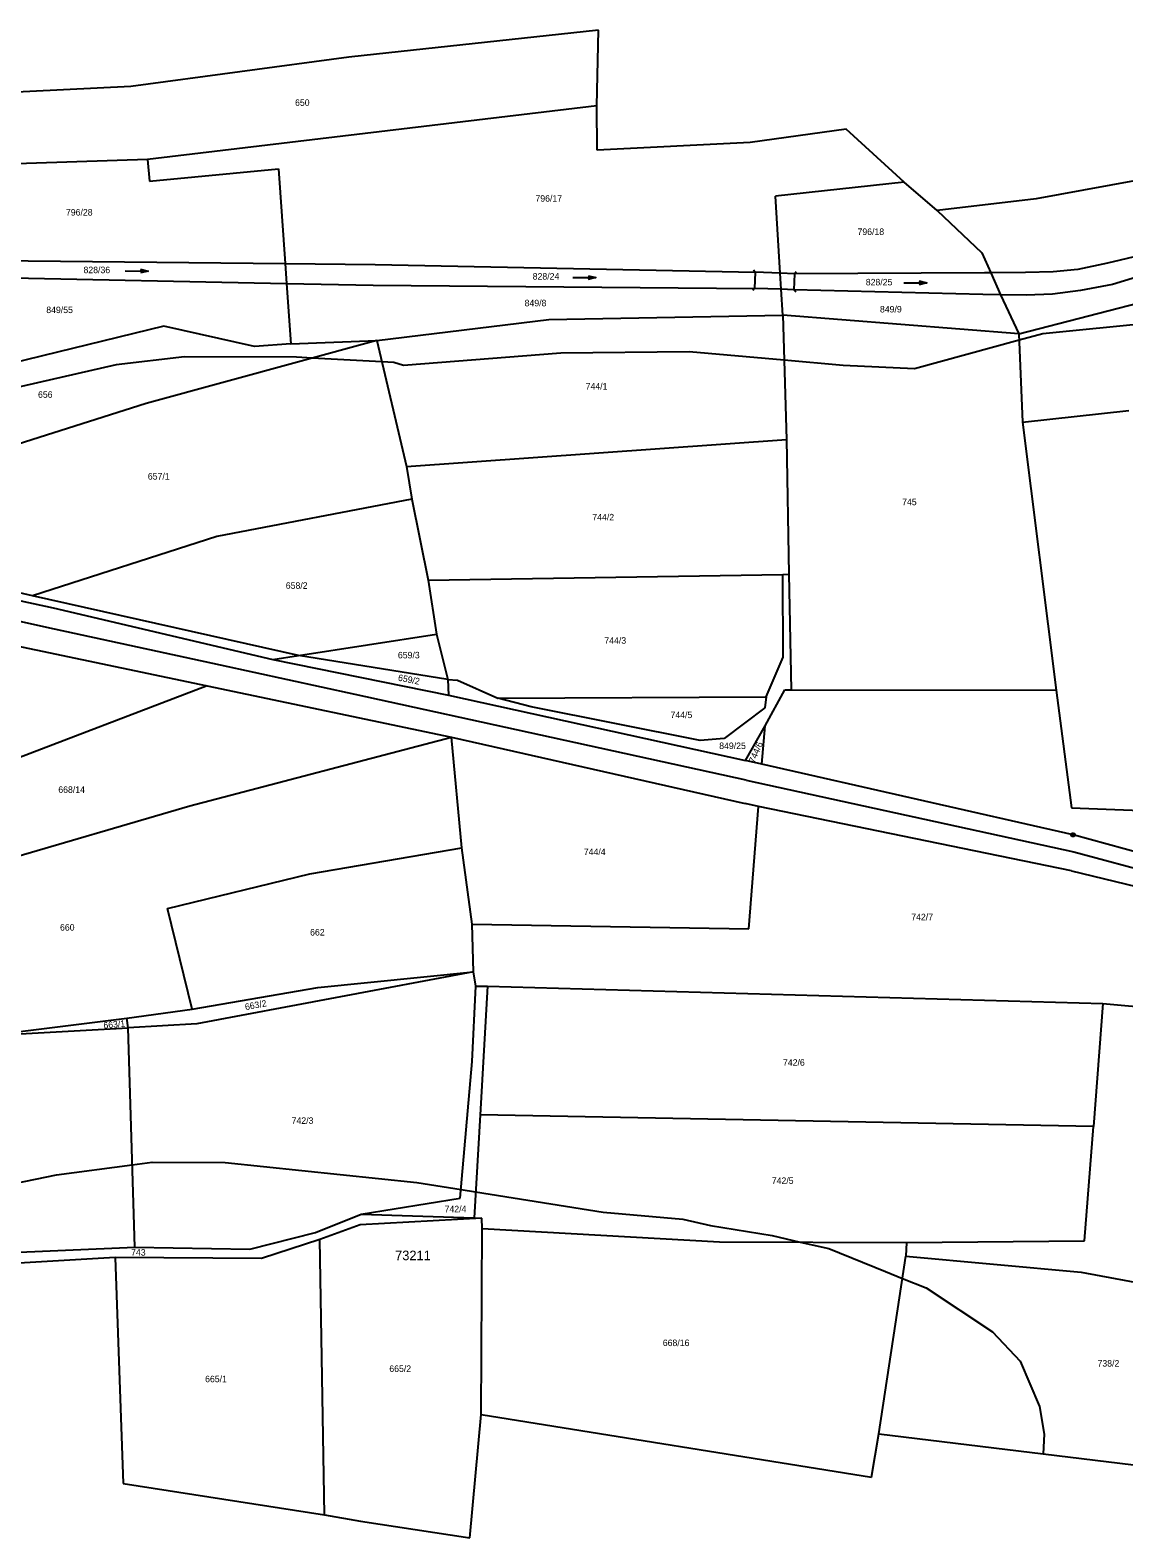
# Model space of a CAD drawing. Extents: x -789470 to -786707, y -1118640 to -1114455.
# Drawn here: x -789008.6 to -788723, y -1114869.5 to -1114476 of the extents above; entities that cross this region are included whole.
import ezdxf

# ---------------------------------------------------------------- set-up
doc = ezdxf.new("R2010")
doc.units = 0
for name, color, linetype in [('1', 7, 'Continuous'), ('11', 7, 'Continuous'), ('2', 7, 'Continuous'), ('3', 7, 'Continuous'), ('4', 7, 'Continuous'), ('6', 7, 'Continuous'), ('8', 7, 'Continuous')]:
    doc.layers.add(name, color=color, linetype=linetype)

msp = doc.modelspace()

# ---------------------------------------------------------------- linework, layer by layer
at = {"layer": '1'}
for p, q in [((-788860.22, -1114476), (-788925.35, -1114483.02)), ((-788860.65, -1114495.76), (-788860.22, -1114476)), ((-788925.35, -1114483.02), (-788982.26, -1114490.73)), ((-788982.26, -1114490.73), (-789030.25, -1114493.04)), ((-788860.65, -1114495.76), (-788977.92, -1114509.77)), ((-788860.57, -1114507.36), (-788860.65, -1114495.76)), ((-788795.54, -1114501.83), (-788820.58, -1114505.34)), ((-788780.41, -1114515.68), (-788795.54, -1114501.83)), ((-788820.58, -1114505.34), (-788860.57, -1114507.36)), ((-788977.92, -1114509.77), (-789040.51, -1114511.82)), ((-788977.92, -1114509.77), (-788977.42, -1114515.41)), ((-788977.42, -1114515.41), (-788943.76, -1114512.16)), ((-788943.76, -1114512.16), (-788942, -1114536.9)), ((-788705.61, -1114512.65), (-788745.95, -1114520.06)), ((-788780.41, -1114515.68), (-788813.99, -1114519.29)), ((-788812.75, -1114539.42), (-788813.99, -1114519.29)), ((-788771.75, -1114523.06), (-788780.41, -1114515.68)), ((-788745.95, -1114520.06), (-788771.75, -1114523.06)), ((-788771.75, -1114523.06), (-788760.13, -1114534.14)), ((-788750.44, -1114555.28), (-788649.58, -1114529.02)), ((-788760.13, -1114534.14), (-788757.8, -1114539.34)), ((-788718.84, -1114534.86), (-788727.34, -1114536.81)), ((-789021.34, -1114536.08), (-788942, -1114536.9)), ((-788942, -1114536.9), (-788941.63, -1114542.1)), ((-788942, -1114536.9), (-788918.51, -1114537.14)), ((-788918.51, -1114537.14), (-788819.27, -1114539.17)), ((-788741.49, -1114539.08), (-788748.69, -1114539.26)), ((-788735.01, -1114538.51), (-788741.49, -1114539.08)), ((-788727.34, -1114536.81), (-788735.01, -1114538.51)), ((-789021.49, -1114540.49), (-788941.63, -1114542.1)), ((-788941.63, -1114542.1), (-788940.51, -1114557.89)), ((-788941.63, -1114542.1), (-788919.01, -1114542.55)), ((-788919.01, -1114542.55), (-788819.42, -1114543.39)), ((-788812.75, -1114539.42), (-788819.27, -1114539.17)), ((-788812.49, -1114543.63), (-788812.75, -1114539.42)), ((-788809.05, -1114539.56), (-788812.75, -1114539.42)), ((-788759.42, -1114539.35), (-788809.05, -1114539.56)), ((-788757.8, -1114539.34), (-788759.42, -1114539.35)), ((-788748.69, -1114539.26), (-788757.8, -1114539.34)), ((-788757.8, -1114539.34), (-788755.23, -1114545.05)), ((-788726.02, -1114542.39), (-788734.31, -1114543.93)), ((-788717.73, -1114539.86), (-788726.02, -1114542.39)), ((-788812.49, -1114543.63), (-788819.42, -1114543.39)), ((-788812.08, -1114550.36), (-788812.49, -1114543.63)), ((-788809.16, -1114543.75), (-788812.49, -1114543.63)), ((-788759.81, -1114544.99), (-788809.16, -1114543.75)), ((-788755.23, -1114545.05), (-788759.81, -1114544.99)), ((-788755.23, -1114545.05), (-788750.44, -1114555.28)), ((-788748.54, -1114545.13), (-788755.23, -1114545.05)), ((-788741.64, -1114544.89), (-788748.54, -1114545.13)), ((-788734.31, -1114543.93), (-788741.64, -1114544.89)), ((-788873.19, -1114551.53), (-788812.08, -1114550.36)), ((-788750.44, -1114555.28), (-788812.08, -1114550.36)), ((-788812.08, -1114550.36), (-788811.07, -1114582.85)), ((-788973.71, -1114553.25), (-789058.59, -1114574)), ((-788950.02, -1114558.61), (-788973.71, -1114553.25)), ((-788918.07, -1114556.96), (-788873.19, -1114551.53)), ((-788918.07, -1114556.96), (-788978.27, -1114573.47)), ((-788940.51, -1114557.89), (-788950.02, -1114558.61)), ((-788940.51, -1114557.89), (-788918.07, -1114556.96)), ((-788918.07, -1114556.96), (-788910.33, -1114589.9)), ((-788750.44, -1114555.28), (-788749.5, -1114578.32)), ((-788978.27, -1114573.47), (-789057.48, -1114598.57)), ((-788749.5, -1114578.32), (-788721.73, -1114575.26)), ((-788749.5, -1114578.32), (-788740.67, -1114648.25)), ((-788910.33, -1114589.9), (-788811.07, -1114582.85)), ((-788811.07, -1114582.85), (-788810.49, -1114618)), ((-788910.33, -1114589.9), (-788908.92, -1114598.39)), ((-788908.92, -1114598.39), (-788959.84, -1114608.12)), ((-788908.92, -1114598.39), (-788904.63, -1114619.6)), ((-788959.84, -1114608.12), (-789007.92, -1114623.62)), ((-789061.16, -1114614.19), (-789002.52, -1114626.82)), ((-789007.92, -1114623.62), (-789043.9, -1114615.51)), ((-788904.63, -1114619.6), (-788812.08, -1114618.04)), ((-788904.63, -1114619.6), (-788902.51, -1114633.65)), ((-788812.08, -1114618.04), (-788810.49, -1114618)), ((-788811.99, -1114639.69), (-788812.08, -1114618.04)), ((-788810.49, -1114618), (-788809.85, -1114648.14)), ((-788938.55, -1114639.25), (-789007.92, -1114623.62)), ((-789002.52, -1114626.82), (-788945.18, -1114640.28)), ((-789033.04, -1114632.27), (-788962.34, -1114647.14)), ((-788938.55, -1114639.25), (-788902.51, -1114633.65)), ((-788902.51, -1114633.65), (-788899.53, -1114645.51)), ((-788945.18, -1114640.28), (-788938.55, -1114639.25)), ((-788945.18, -1114640.28), (-788899.34, -1114649.59)), ((-788899.53, -1114645.51), (-788938.55, -1114639.25)), ((-788816.4, -1114650.04), (-788811.99, -1114639.69)), ((-788962.34, -1114647.14), (-789068.19, -1114687.52)), ((-788962.34, -1114647.14), (-788898.55, -1114660.57)), ((-788899.53, -1114645.51), (-788896.98, -1114645.63)), ((-788899.53, -1114645.51), (-788899.34, -1114649.59)), ((-788896.98, -1114645.63), (-788886.49, -1114650.35)), ((-788816.69, -1114657.55), (-788811.51, -1114648.21)), ((-788811.51, -1114648.21), (-788809.85, -1114648.14)), ((-788809.85, -1114648.14), (-788740.67, -1114648.25)), ((-788740.67, -1114648.25), (-788736.73, -1114679)), ((-788899.34, -1114649.59), (-788821.82, -1114666.61)), ((-788886.49, -1114650.35), (-788816.4, -1114650.04)), ((-788877.76, -1114652.59), (-788886.49, -1114650.35)), ((-788833.62, -1114661.44), (-788877.76, -1114652.59)), ((-788816.78, -1114652.84), (-788827.38, -1114660.85)), ((-788816.4, -1114650.04), (-788816.78, -1114652.84)), ((-788966.91, -1114678.44), (-788898.55, -1114660.57)), ((-788895.88, -1114689.44), (-788898.55, -1114660.57)), ((-788898.55, -1114660.57), (-788821.94, -1114677.87)), ((-788827.38, -1114660.85), (-788833.62, -1114661.44)), ((-788821.82, -1114666.61), (-788816.69, -1114657.55)), ((-788817.52, -1114667.59), (-788816.69, -1114657.55)), ((-788817.52, -1114667.59), (-788821.82, -1114666.61)), ((-788736.3, -1114686.03), (-788817.52, -1114667.59)), ((-789033.32, -1114697.94), (-788966.91, -1114678.44)), ((-788818.39, -1114678.6), (-788821.94, -1114677.87)), ((-788820.98, -1114710.53), (-788818.39, -1114678.6)), ((-788736.68, -1114695.45), (-788818.39, -1114678.6)), ((-788736.73, -1114679), (-788676.01, -1114681.19)), ((-788700.64, -1114695.78), (-788736.3, -1114686.03)), ((-788935.57, -1114696.21), (-788895.88, -1114689.44)), ((-788893.16, -1114709.32), (-788895.88, -1114689.44)), ((-788972.72, -1114705.22), (-788935.57, -1114696.21)), ((-788736.68, -1114695.45), (-788712.4, -1114701.34)), ((-788966.28, -1114731.57), (-788972.72, -1114705.22)), ((-788892.8, -1114721.82), (-788893.16, -1114709.32)), ((-788893.16, -1114709.32), (-788820.98, -1114710.53)), ((-788892.8, -1114721.82), (-788965.07, -1114735.37)), ((-788933.42, -1114725.88), (-788892.8, -1114721.82)), ((-788892.21, -1114725.51), (-788892.8, -1114721.82)), ((-788966.28, -1114731.57), (-788933.42, -1114725.88)), ((-788893.17, -1114745.17), (-788892.21, -1114725.51)), ((-788892.21, -1114725.51), (-788889.17, -1114725.56)), ((-788889.17, -1114725.56), (-788891.11, -1114759.07)), ((-788889.17, -1114725.56), (-788728.52, -1114730.08)), ((-788983.29, -1114733.88), (-788966.28, -1114731.57)), ((-788728.52, -1114730.08), (-788730.98, -1114762.14)), ((-788728.52, -1114730.08), (-788646.02, -1114737.19)), ((-789020.4, -1114738.52), (-788983.29, -1114733.88)), ((-788982.99, -1114736.42), (-788983.29, -1114733.88)), ((-788965.07, -1114735.37), (-788982.99, -1114736.42)), ((-789020.4, -1114738.52), (-788982.99, -1114736.42)), ((-788981.24, -1114793.65), (-788982.99, -1114736.42)), ((-788896.26, -1114780.89), (-788893.17, -1114745.17)), ((-788891.11, -1114759.07), (-788892.67, -1114785.99)), ((-788730.98, -1114762.14), (-788891.11, -1114759.07)), ((-788733.28, -1114792.03), (-788730.98, -1114762.14)), ((-788922.18, -1114785.03), (-788896.26, -1114780.89)), ((-788934.1, -1114789.79), (-788922.18, -1114785.03)), ((-788890.68, -1114786.05), (-788922.39, -1114787.81)), ((-788922.18, -1114785.03), (-788892.67, -1114785.99)), ((-788892.67, -1114785.99), (-788890.68, -1114786.05)), ((-788890.53, -1114788.77), (-788890.68, -1114786.05)), ((-788951.2, -1114794.13), (-788934.1, -1114789.79)), ((-788922.39, -1114787.81), (-788932.94, -1114791.62)), ((-788890.79, -1114837.34), (-788890.53, -1114788.77)), ((-788890.53, -1114788.77), (-788828.56, -1114792.24)), ((-789047.11, -1114796.42), (-788981.24, -1114793.65)), ((-788981.24, -1114793.65), (-788951.2, -1114794.13)), ((-788932.94, -1114791.62), (-788948.17, -1114796.57)), ((-788931.72, -1114863.5), (-788932.94, -1114791.62)), ((-788828.56, -1114792.24), (-788779.75, -1114792.43)), ((-788779.75, -1114792.43), (-788779.95, -1114796.03)), ((-788779.75, -1114792.43), (-788733.28, -1114792.03)), ((-788986.34, -1114796.35), (-789043.29, -1114799.67)), ((-788948.17, -1114796.57), (-788986.34, -1114796.35)), ((-788986.34, -1114796.35), (-788984.29, -1114855.31)), ((-788786.98, -1114842.37), (-788779.95, -1114796.03)), ((-788779.95, -1114796.03), (-788734.14, -1114800.17)), ((-788734.14, -1114800.17), (-788607.43, -1114823.95)), ((-788893.82, -1114869.52), (-788890.79, -1114837.34)), ((-788890.79, -1114837.34), (-788788.93, -1114853.7)), ((-788788.93, -1114853.7), (-788786.98, -1114842.37)), ((-788786.98, -1114842.37), (-788682.87, -1114855.1)), ((-788984.29, -1114855.31), (-788931.72, -1114863.5)), ((-788931.72, -1114863.5), (-788922.32, -1114865.2)), ((-788922.32, -1114865.2), (-788893.82, -1114869.52))]:
    msp.add_line(p, q, dxfattribs=at)
at = {"layer": '11'}
for points in [[(-788715.35, -1114552.35), (-788744.16, -1114555.22), (-788750.37, -1114556.93), (-788777.65, -1114564.42), (-788796.29, -1114563.51), (-788811.71, -1114562.17), (-788836.53, -1114560), (-788870, -1114560.32), (-788911.1, -1114563.57), (-788913.64, -1114562.71), (-788916.76, -1114562.55), (-788934.93, -1114561.58), (-788939.06, -1114561.36), (-788968.29, -1114561.27), (-788986.09, -1114563.33), (-789017.03, -1114570.42)], [(-789024.16, -1114779.36), (-789001.7, -1114774.78), (-788981.9, -1114772.16), (-788976.7, -1114771.48), (-788957.63, -1114771.54), (-788907.65, -1114776.78), (-788896.06, -1114778.62), (-788892.28, -1114779.23), (-788858.94, -1114784.55), (-788838.18, -1114786.31), (-788830.99, -1114788.02), (-788814.89, -1114790.61), (-788807.51, -1114792.32), (-788800.07, -1114794.04), (-788785.25, -1114800.01), (-788780.83, -1114801.8), (-788774.67, -1114804.28), (-788757.32, -1114815.75), (-788750.13, -1114823.39), (-788745.06, -1114835.25), (-788743.8, -1114842.45), (-788744.08, -1114847.62)]]:
    msp.add_lwpolyline(points, dxfattribs=at)
at = {"layer": '3'}
for p, q in [((-788983.76, -1114538.8), (-788977.76, -1114538.92)), ((-788866.91, -1114540.6), (-788860.91, -1114540.6)), ((-788780.5, -1114541.96), (-788774.5, -1114541.96))]:
    msp.add_line(p, q, dxfattribs=at)
for points in [[(-788979.75, -1114538.38), (-788977.76, -1114538.92), (-788979.77, -1114539.38)], [(-788862.91, -1114540.1), (-788860.91, -1114540.6), (-788862.91, -1114541.1)], [(-788776.5, -1114541.46), (-788774.5, -1114541.96), (-788776.5, -1114542.46)]]:
    msp.add_lwpolyline(points, dxfattribs=at)
at = {"layer": '4'}
for p, q in [((-788819.27, -1114539.17), (-788819.76, -1114538.66)), ((-788809.05, -1114539.56), (-788808.58, -1114539.03)), ((-788819.27, -1114539.17), (-788819.42, -1114543.39)), ((-788809.05, -1114539.56), (-788809.16, -1114543.75)), ((-788819.42, -1114543.39), (-788819.89, -1114543.92)), ((-788809.16, -1114543.75), (-788808.69, -1114544.28))]:
    msp.add_line(p, q, dxfattribs=at)
at = {"layer": '6'}
for p, q in [((-789004.18, -1114631.89), (-789063.67, -1114618.94)), ((-788958.85, -1114641.77), (-789004.18, -1114631.89)), ((-788923.68, -1114649.41), (-788958.85, -1114641.77)), ((-788875.28, -1114659.98), (-788923.68, -1114649.41)), ((-788821.64, -1114671.77), (-788875.28, -1114659.98)), ((-788821.64, -1114671.77), (-788736.11, -1114690.43)), ((-788736.11, -1114690.43), (-788706.42, -1114698.5))]:
    msp.add_line(p, q, dxfattribs=at)
at = {"layer": '8'}
msp.add_line((-788736.42, -1114686.03), (-788736.18, -1114686.03), dxfattribs=at)
msp.add_lwpolyline([(-788736.15, -1114685.55), (-788735.9, -1114685.73), (-788735.8, -1114686.02), (-788735.9, -1114686.31), (-788736.15, -1114686.49), (-788736.46, -1114686.49), (-788736.71, -1114686.31), (-788736.81, -1114686.02), (-788736.71, -1114685.73), (-788736.46, -1114685.55)], close=True, dxfattribs=at)

# ---------------------------------------------------------------- texts
at = {"layer": '11'}
msp.add_text('73211', height=2.5, dxfattribs=at).set_placement((-788913.28, -1114797.05))
at = {"layer": '2'}
for s, p in [('650', (-788939.41, -1114495.76)), ('796/17', (-788876.65, -1114520.77)), ('796/28', (-788999.22, -1114524.39)), ('796/18', (-788792.57, -1114529.46)), ('828/36', (-788994.64, -1114539.43)), ('828/24', (-788877.37, -1114541.11)), ('828/25', (-788790.41, -1114542.62)), ('849/8', (-788879.48, -1114548.08)), ('849/55', (-789004.36, -1114549.85)), ('849/9', (-788786.71, -1114549.68)), ('656', (-789006.52, -1114571.96)), ('744/1', (-788863.54, -1114569.81)), ('657/1', (-788977.84, -1114593.31)), ('745', (-788780.92, -1114600)), ('744/2', (-788861.8, -1114603.96)), ('658/2', (-788941.83, -1114621.82)), ('744/3', (-788858.66, -1114636.15)), ('659/3', (-788912.56, -1114639.97)), ('744/5', (-788841.39, -1114655.56)), ('849/25', (-788828.67, -1114663.64)), ('668/14', (-789001.22, -1114675.08)), ('744/4', (-788864.02, -1114691.3)), ('742/7', (-788778.54, -1114708.33)), ('660', (-789000.77, -1114711.03)), ('662', (-788935.48, -1114712.31)), ('742/6', (-788812.03, -1114746.29)), ('742/3', (-788940.3, -1114761.46)), ('742/5', (-788814.95, -1114777.15)), ('742/4', (-788900.37, -1114784.55)), ('743', (-788982.22, -1114795.86)), ('668/16', (-788843.4, -1114819.47)), ('665/2', (-788914.8, -1114826.22)), ('738/2', (-788729.91, -1114824.83)), ('665/1', (-788962.89, -1114828.91))]:
    msp.add_text(s, height=1.7, dxfattribs=at).set_placement(p)
for s, rotation, p in [('659/2', 349.0459, (-788912.63, -1114645.77)), ('744/6', 66.8069, (-788819.46, -1114667.42)), ('663/2', 10.5424, (-788952.32, -1114731.81)), ('663/1', 5.3858, (-788989.37, -1114736.62))]:
    msp.add_text(s, height=1.7, rotation=rotation, dxfattribs=at).set_placement(p)

doc.saveas('drawing.dxf')
